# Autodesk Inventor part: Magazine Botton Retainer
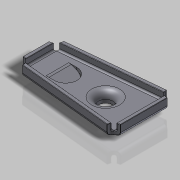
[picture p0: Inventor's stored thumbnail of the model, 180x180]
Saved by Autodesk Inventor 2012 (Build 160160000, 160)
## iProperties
Company: MH Vaaben Teknik
Category: Sten MK II Magazine
Created: 2011-12
Part Number: Magazine Botton Retainer
Material: Steel, Mild
Document SubType Name: Modeling
Designer: Michael Høgh
Density: 7.86 g/cm^3
Project: Sten MK II
Mass: 4.59343 g
Surface Area: 12.7332 cm^2
Volume: 0.584406 cm^3
Engineer: MH Vaaben Teknik
Author: Michael Høgh
Title: Magazine Bottom Retainer
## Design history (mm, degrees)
sketch "Sketch1"
  geometry: L1 (-15.5, 8.75)-(15.5, 8.75); L2 (15.5, 8.75)-(15.5, -8.75); L3 (15.5, -8.75)-(-15.5, -8.75); L4 (-15.5, -8.75)-(-15.5, 8.75); L5 (15.5, 8.75)-(-15.5, 5.75); L6 (15.5, -8.75)-(-15.5, -5.75); 3 further points
  constraints: 12 end point, 2 midpoint, 2 parallel, 2 point on line, 1 horizontal, 1 horizontal alignment, 1 perpendicular, 1 vertical alignment
  dimensions: "d0" = 31 distance of L1.start L1.end; "d1" = 17.5 distance of L1.end L2.end; "d2" = 3 distance of L5.end L1.start; "d3" = 3 distance of L6.end L3.end
extrude "Extrusion1" new body sketch "Sketch1" distance "d8" = 1; taper "d9" = 0 deg
sketch "Sketch3"
  geometry: L1 (15.5, -8.75)-(-15.5, -5.75) reference; L2 (15.5, 8.75)-(15.5, -8.75) reference; L3 (-15.5, 5.75)-(15.5, 8.75) reference; L4 (-15.5, -5.75)-(-15.5, 5.75) reference; L5 (15.5, 8.75)-(-15.5, 5.75); L6 (-15.5, 5.75)-(-15.5, -5.75); L7 (-15.5, -5.75)-(15.5, -8.75); L8 (15.5, 8.75)-(15.5, -8.75); L9 (-14.5, 4.842)-(14.5, 7.649); L10 (14.5, 7.649)-(14.5, -7.649); L11 (14.5, -7.649)-(-14.5, -4.842); L12 (-14.5, -4.842)-(-14.5, 4.842); 1 further point
  constraints: 16 end point, 4 collinear, 3 other
  dimensions: "d16" = 1 distance between parallel lines of L3 L9
extrude "Extrusion3" join sketch "Sketch3" distance "d17" = 2; taper "d18" = 0 deg
sketch "Sketch4"
  geometry: C1 r 2 at (-15.5, 5.75); C2 r 2 at (-15.5, -5.75); C3 r 2 at (15.5, -8.75); C4 r 2 at (15.5, 8.75); 5 further points
  constraints: 4 centre point, 4 coincident
  dimensions: "d19" = 4 diameter of C1; "d20" = 4 diameter of C2; "d21" = 4 diameter of C3; "d22" = 4 diameter of C4
extrude "Extrusion4" cut sketch "Sketch4" stored distance "d23" = 2; taper "d24" = 0 deg
sketch "Sketch5"
  geometry: L1 (15.5, 6.75)-(15.5, -6.75) reference; C1 r 2 at (4.5, 0); 1 further point
  constraints: 1 centre point
  dimensions: "d25" = 4 diameter of C1; "d33" = 11 distance from line of C1.centre L1
extrude "Extrusion5" cut sketch "Sketch5" stored distance "d26" = 2; taper "d27" = 0 deg
sketch "Sketch6"
  geometry: C1 r 2 at (-4.5, 0) reference; C2 r 3 at (-4.5, 0); 1 further point
  constraints: 1 centre point, 1 coincident
  dimensions: "d28" = 6 diameter of C2
extrude "Extrusion6" join sketch "Sketch6" distance "d29" = 2; taper "d30" = 0 deg
fillet "Fillet1" dims "d31" = 1
fillet "Fillet2" dims "d32" = 2
fillet "Fillet3" dims "d34" = 1
fillet "Fillet4" dims "d35" = 0.5
chamfer "Chamfer1" distance "d36" = 0.1; stored, may be unused: second distance "d37" = 2, angle "d38" = 45 deg
chamfer "Chamfer2" distance "d39" = 0.1; stored, may be unused: second distance "d40" = 2, angle "d41" = 45 deg
fillet "Fillet5" dims "d42" = 0.2
chamfer "Chamfer3" distance "d43" = 0.1; stored, may be unused: second distance "d44" = 2, angle "d45" = 45 deg
sketch "Sketch7"
  geometry: L1 (15.5, -6.65)-(15.5, 6.65) reference; L2 (-7, 3.25)-(-11, 3.25); L3 (-11, 3.25)-(-11, -3.25); L4 (-11, -3.25)-(-7, -3.25); L5 (-9, 3.25)-(-9, -3.25); A1 r 3.25 centre (-7, 0) between (-7, 3.25) and (-7, -3.25); 1 further point
  constraints: 8 end point, 2 midpoint, 2 perpendicular, 2 point on circle, 2 tangent, 1 centre point
  dimensions: "d46" = 6.5 diameter of A1; "d47" = 22.5 distance from line of A1.centre L1; "d48" = 2 distance from line of L5 A1.centre; "d49" = 6.5 distance of L2.end L3.end
extrude "Extrusion7" cut sketch "Sketch7" stored distance "d50" = 2; taper "d51" = 0 deg
workplane "Work Plane2"
sketch "Sketch9"
  geometry: L1 (-4.875, -2)-(-4.875, 0); L2 (2.228, 5.946)-(-5.478, 5.946) reference; L3 (-4.875, 0)-(1.625, 0); L4 (1.625, 0)-(1.625, -2); L5 (-4.875, 0)-(1.625, 0) reference; A1 r 3.25 centre (-1.625, -2) between (-4.875, -2) and (1.625, -2); 1 further point
  constraints: 6 end point, 2 perpendicular, 2 point on circle, 2 tangent, 1 centre point
  dimensions: "d61" = 6.5 diameter of A1; "d62" = 2 distance from line of L3 A1.centre; "d63" = 6.5 distance of L1.end L3.end; "d64" = 0 distance between parallel lines of L5 L3
extrude "Extrusion9" join sketch "Sketch9" distance "d65" = 1; taper "d66" = 0 deg
fillet "Fillet6" dims "d67" = 2
fillet "Fillet7" dims "d68" = 1
body "Solid1"
other parameters: "d60" = 290 deg
